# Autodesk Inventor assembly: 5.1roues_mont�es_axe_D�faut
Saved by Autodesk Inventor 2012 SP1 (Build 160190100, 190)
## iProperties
Created: 2011-01
Part Number: 5.1roues_mont�es_axe_D�faut
Document SubType Name: Assembly
Designer: eric
Mass: 610.809 g
Surface Area: 3296.9 cm^2
Volume: 610.809 cm^3
Density: 1 g/cm^3
Author: eric
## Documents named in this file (5)
- D:\Cours\Inventor salle SI\chariot_de_golf_2008\chariot_de_golf_trolem\5.1roues_montees_axe_Defaut.iam
- D:\Cours\Inventor salle SI\chariot_de_golf_2008\chariot_de_golf_trolem\5.1Anneaugrifaxe12_Defaut.ipt
- D:\Cours\Inventor salle SI\chariot_de_golf_2008\chariot_de_golf_trolem\9envoliveur_Defaut.ipt
- D:\Cours\Inventor salle SI\chariot_de_golf_2008\chariot_de_golf_trolem\5.1roue_avant_montee_Defaut.iam
- D:\Cours\Inventor salle SI\chariot_de_golf_2008\chariot_de_golf_trolem\5.1axe e12_Defaut.ipt
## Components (7 placed, 4 different names)
1. 9envoliveur_Defaut:1
2. 5.1roue_avant_montee_Defaut:1 [sub-assembly]
3. 5.1Anneaugrifaxe12_Defaut:3
4. 9envoliveur_Defaut:2
5. 5.1axe e12_Defaut:1
6. 5.1roue_avant_montee_Defaut:2 [sub-assembly]
7. 5.1Anneaugrifaxe12_Defaut:2
